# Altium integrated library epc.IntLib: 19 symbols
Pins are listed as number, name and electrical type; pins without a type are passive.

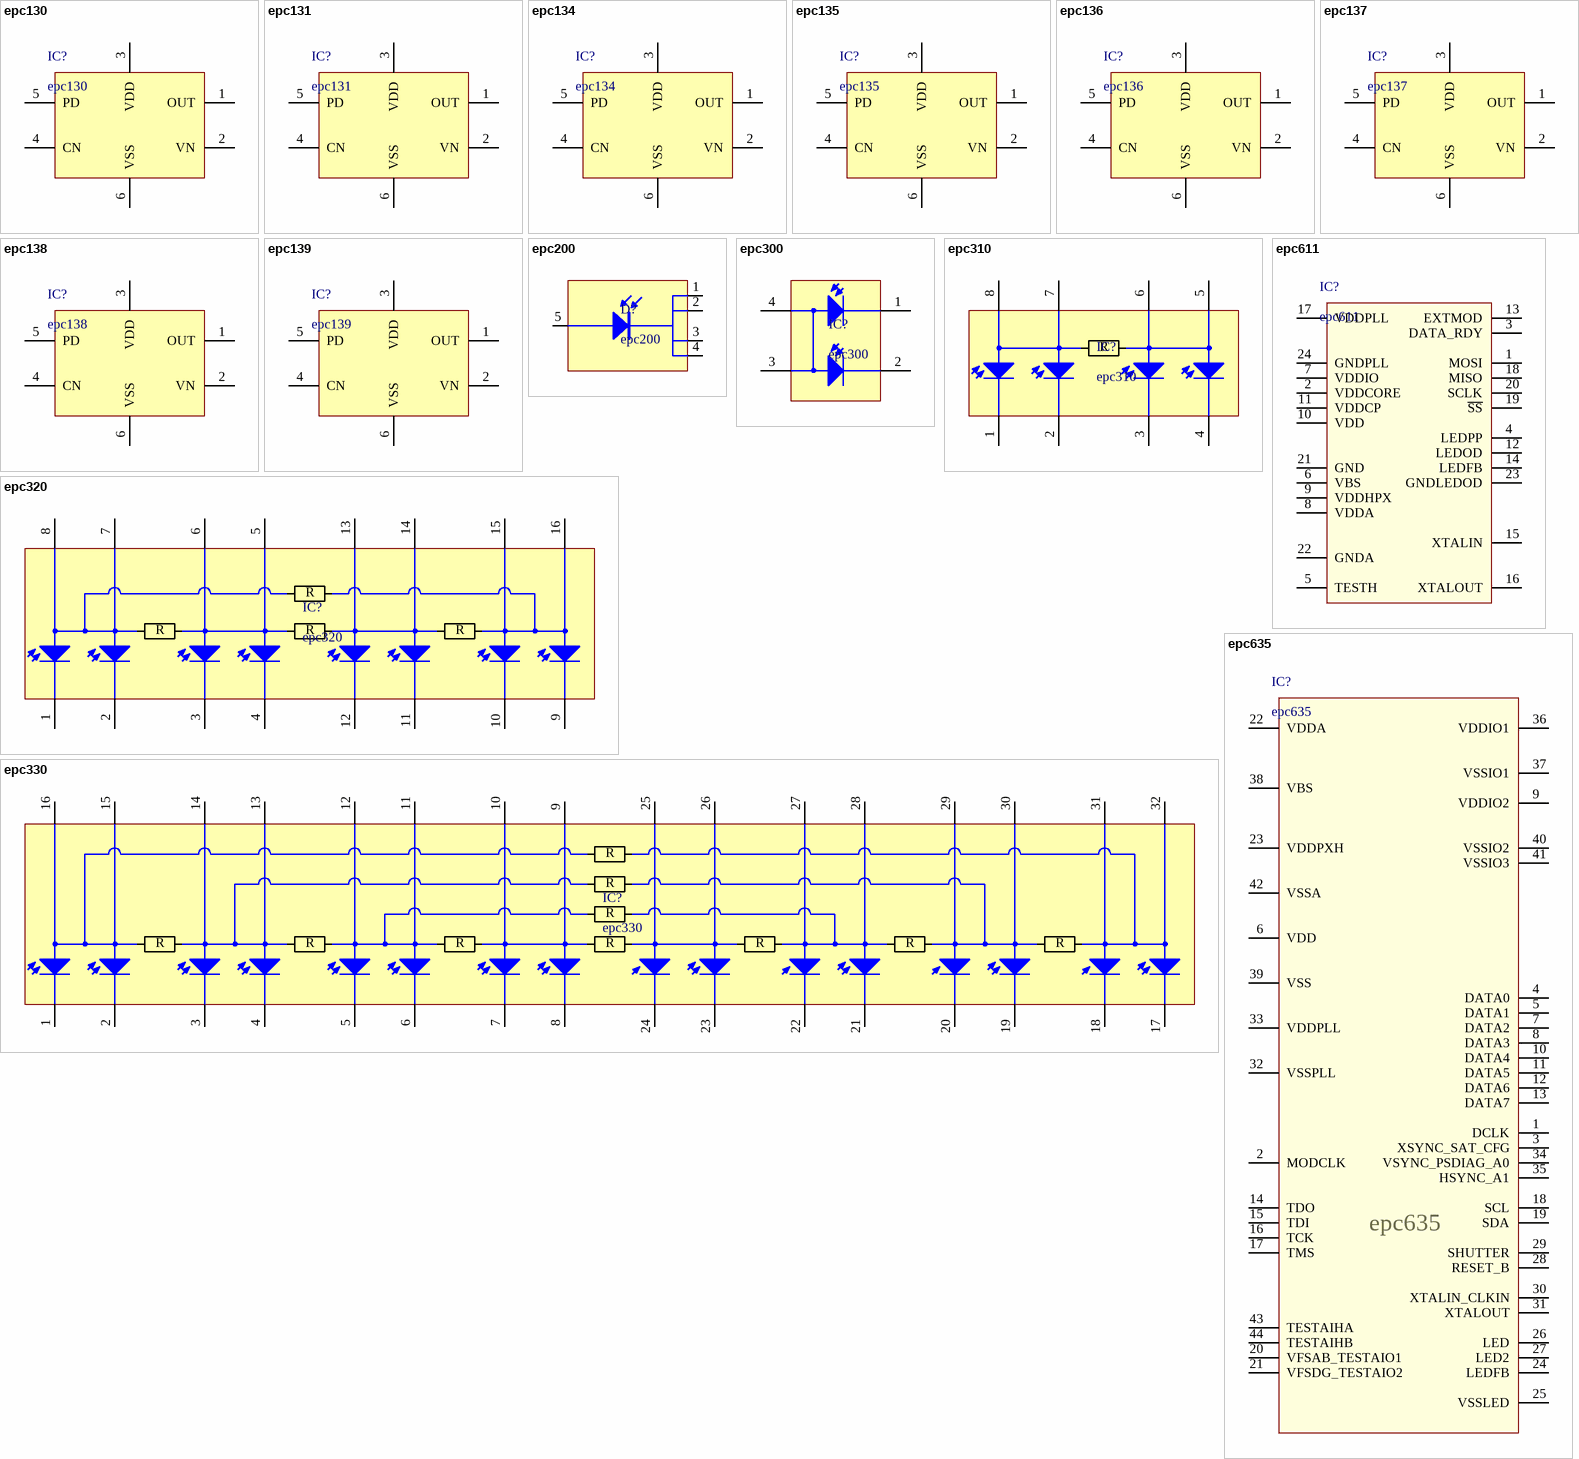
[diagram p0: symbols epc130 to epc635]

## epc130
designator IC?
epc130, Photo-receiver Amplifier with analog output; Part number: P100 010; Manufacturer: ESPROS Photonics; Order information: epc130-CSP6-B; Schlib reviewed: 230418/SHA
footprint CSP 2x3 560x430 (Footprint not found)
pins: 1 OUT, 2 VN, 3 VDD, 4 CN, 5 PD, 6 VSS

## epc131
designator IC?
epc131, Photo-receiver Amplifier with analog output; Part number: P100 011; Manufacturer: ESPROS Photonics; Order information: epc131-CSP6-D; Schlib reviewed: 230418/SHA
footprint CSP 2x3 560x430 (CSP 2x3)
pins: 1 OUT, 2 VN, 3 VDD, 4 CN, 5 PD, 6 VSS

## epc134
designator IC?
epc134, Photo-receiver Amplifier with digital output; Part number: P100 491; Manufacturer: ESPROS Photonics; Order information: epc134-CSP6-D; Schlib reviewed: 230418/SHA
footprint CSP 2x3 560x430 (CSP 2x3)
pins: 1 OUT, 2 VN, 3 VDD, 4 CN, 5 PD, 6 VSS

## epc135
designator IC?
epc135, Photo-receiver Amplifier with digital output; Part number: P100 012; Manufacturer: ESPROS Photonics; Order information: epc135-CSP6-B; Schlib reviewed: 230418/SHA
footprint CSP 2x3 560x430 (CSP 2x3)
pins: 1 OUT, 2 VN, 3 VDD, 4 CN, 5 PD, 6 VSS

## epc136
designator IC?
epc136, Photo-receiver Amplifier with digital output; Part number: P100 013; Manufacturer: ESPROS Photonics; Order information: epc136-CSP6-B; Schlib reviewed: 230418/SHA
footprint CSP 2x3 560x430 (CSP 2x3)
pins: 1 OUT, 2 VN, 3 VDD, 4 CN, 5 PD, 6 VSS

## epc137
designator IC?
epc137, Photo-receiver Amplifier with digital output; Part number: P100 152; Manufacturer: ESPROS Photonics; Order information: epc137-CSP6-D; Schlib reviewed: 230418/SHA
footprint CSP 2x3 560x430 (CSP 2x3)
pins: 1 OUT, 2 VN, 3 VDD, 4 CN, 5 PD, 6 VSS

## epc138
designator IC?
epc138, Photo-receiver Amplifier with digital output; Part number: P100 109; Manufacturer: ESPROS Photonics; Order information: epc138-CSP6-D; Schlib reviewed: 230418/SHA
footprint CSP 2x3 560x430 (CSP 2x3)
pins: 1 OUT, 2 VN, 3 VDD, 4 CN, 5 PD, 6 VSS

## epc139
designator IC?
epc139, Photo-receiver Amplifier with digital output; Part number: P100 014; Manufacturer: ESPROS Photonics; Order information: epc139-CSP6-B; Schlib reviewed: 230418/SHA
footprint CSP 2x3 560x430 (CSP 2x3)
pins: 1 OUT, 2 VN, 3 VDD, 4 CN, 5 PD, 6 VSS

## epc200
designator D?
epc200, High sensitive photodiode; Part number: P100 179; Manufacturer: ESPROS Photonics; Order information: epc200-CSP5; Schlib reviewed: 230418/SHA; Pcblib reviewed: already existed
footprint epc200
pins: 1 C, 2 C, 3 C, 4 C, 5 A

## epc300
designator IC?
epc300, high sensitive photodiode array with 2 photodiodes; Part number: P100 049; Manufacturer: ESPROS Photonics; Order information: epc300-CSP4-001; Schlib reviewed: 230418/SHA
footprint CSP4 (CSP4 Dual Photodiode)
pins: 1 C1, 2 C2, 3 A2, 4 A1

## epc310
designator IC?
epc310, high sensitive photodiode array with 4 photodiodes; Part number: P100 050; Manufacturer: ESPROS Photonics; Order information: epc310-CSP8-001; Schlib reviewed: 230418/SHA
footprint CSP8 (CSP8 Quad Photodiode-Array)
pins: 1 C1, 2 C2, 3 C3, 4 C4, 5 A4, 6 A3, 7 A2, 8 A1

## epc320
designator IC?
epc320, high sensitive photodiode array with 8 photodiodes; Part number: P100 051; Manufacturer: ESPROS Photonics; Order information: epc320-CSP16-001; Schlib reviewed: 230418/SHA
footprint CSP16 (CSP16 Octa Photodiode-Array)
pins: 1 C1, 2 C2, 3 C3, 4 C4, 5 A4, 6 A3, 7 A2, 8 A1, 9 C5, 10 C6, 11 C7, 12 C8, 13 A8, 14 A7, 15 A6, 16 A5

## epc330
designator IC?
epc330, high sensitive photodiode array with 16 photodiodes; Part number: P100 052; Manufacturer: ESPROS Photonics; Order information: epc330-CSP32-001; Schlib reviewed: 230418/SHA
footprint CSP32 (CSP16 hexa Photodiode-Array)
pins: 1 C1, 2 C2, 3 C3, 4 C4, 5 C5, 6 C6, 7 C7, 8 C8, 9 A8, 10 A7, 11 A6, 12 A5, 13 A4, 14 A3, 15 A2, 16 A1, 17 C9, 18 C10, 19 C11, 20 C12, 21 C13, 22 C14, 23 C15, 24 C16, 25 A16, 26 A15, 27 A14, 28 A13, 29 A12, 30 A11, 31 A10, 32 A9

## epc611
designator IC?
epc611, TOF range-finder / 8x8 pixel TOF imager; Part number: P100 378; Manufacturer: ESPROS Photonics; Order information: epc611-CSP-000; SchLib reviewed: 230228/SHA; PcbLib reviewed: 210707/ROD
footprint epc611
pins: 1 MOSI, 2 VDDCORE, 3 DATA_RDY, 4 LEDPP, 5 TESTH, 6 VBS, 7 VDDIO, 8 VDDA, 9 VDDHPX, 10 VDD, 11 VDDCP, 12 LEDOD, 13 EXTMOD, 14 LEDFB, 15 XTALIN, 16 XTALOUT, 17 VDDPLL, 18 MISO, 19 ~{SS}, 20 SCLK, 21 GND, 22 GNDA, 23 GNDLEDOD, 24 GNDPLL

## epc635
designator IC?
epc635-CSP44-003, 3D TOF imager 160 x 60 pixel; Part number: P100 181; Manufacturer: ESPROS Photonics; Schlib reviewed: 230220/SHA; Pcblib reviewed: already existed
footprint epc635_Plane_Top (CSP44 epc635_PL_Top)
pins: 1 DCLK, 2 MODCLK, 3 XSYNC_SAT_CFG, 4 DATA0, 5 DATA1, 6 VDD, 7 DATA2, 8 DATA3, 9 VDDIO2, 10 DATA4, 11 DATA5, 12 DATA6, 13 DATA7, 14 TDO, 15 TDI, 16 TCK, 17 TMS, 18 SCL, 19 SDA, 20 VFSAB_TESTAIO1, 21 VFSDG_TESTAIO2, 22 VDDA, 23 VDDPXH, 24 LEDFB, 25 VSSLED, 26 LED, 27 LED2, 28 RESET_B, 29 SHUTTER, 30 XTALIN_CLKIN, 31 XTALOUT, 32 VSSPLL, 33 VDDPLL, 34 VSYNC_PSDIAG_A0, 35 HSYNC_A1, 36 VDDIO1, 37 VSSIO1, 38 VBS, 39 VSS, 40 VSSIO2, 41 VSSIO3, 42 VSSA, 43 TESTAIHA, 44 TESTAIHB

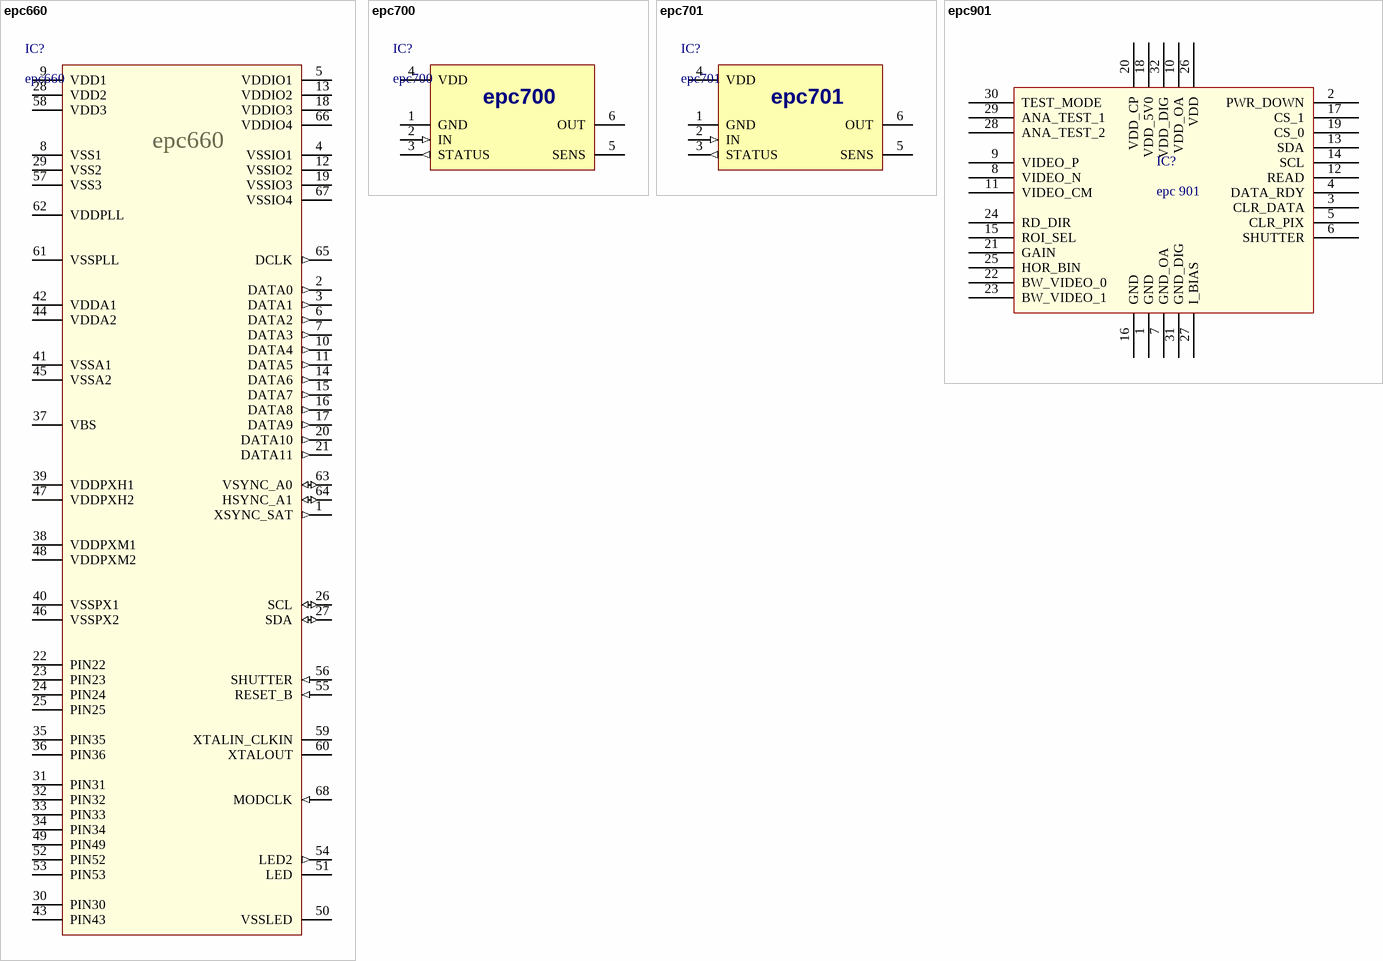
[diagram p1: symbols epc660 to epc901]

## epc660
designator IC?
epc660, 3D TOF imager 320 x 240 pixel; Part number: P100 688; Manufacturer: ESPROS Photonics; Order information: epc660-CSP68-011; Schlib reviewed: 230418/SHA
footprint epc660_Plane_Top (CSP68 epc660_PL_Top)
pins: 1 XSYNC_SAT (out), 2 DATA0 (out), 3 DATA1 (out), 4 VSSIO1 (power), 5 VDDIO1 (power), 6 DATA2 (out), 7 DATA3 (out), 8 VSS1 (power), 9 VDD1 (power), 10 DATA4 (out), 11 DATA5 (out), 12 VSSIO2 (power), 13 VDDIO2 (power), 14 DATA6 (out), 15 DATA7 (out), 16 DATA8 (out), 17 DATA9 (out), 18 VDDIO3 (power), 19 VSSIO3 (power), 20 DATA10 (out), 21 DATA11 (out), 22 PIN22, 23 PIN23, 24 PIN24, 25 PIN25, 26 SCL (io), 27 SDA (io), 28 VDD2 (power), 29 VSS2 (power), 30 PIN30, 31 PIN31, 32 PIN32, 33 PIN33, 34 PIN34, 35 PIN35, 36 PIN36, 37 VBS (power), 38 VDDPXM1 (power), 39 VDDPXH1 (power), 40 VSSPX1 (power), 41 VSSA1 (power), 42 VDDA1 (power), 43 PIN43, 44 VDDA2 (power), 45 VSSA2 (power), 46 VSSPX2 (power), 47 VDDPXH2 (power), 48 VDDPXM2 (power), 49 PIN49, 50 VSSLED (power), 51 LED (oc), 52 PIN52, 53 PIN53, 54 LED2 (out), 55 RESET_B (in), 56 SHUTTER (in), 57 VSS3 (power), 58 VDD3 (power), 59 XTALIN_CLKIN, 60 XTALOUT, 61 VSSPLL (power), 62 VDDPLL (power), 63 VSYNC_A0 (io), 64 HSYNC_A1 (io), 65 DCLK (out), 66 VDDIO4 (power), 67 VSSIO4 (power), 68 MODCLK (in)

## epc700
designator IC?
epc700 General Purpose Output Driver Low-Side Switch CSP-6; Part number: P100 009; Manufacturer: ESPROS Photonics; Order information: epc700-CSP6-A; Schlib reviewed: 230418/SHA
footprint CSP 2x3 560x430 (CSP 2x3)
pins: 1 GND (power), 2 IN (in), 3 STATUS (out), 4 VDD (power), 5 SENS, 6 OUT (oc)

## epc701
designator IC?
epc701 General Purpose Output Driver High-Side Switch CSP-6; Part number: P100 039; Manufacturer: ESPROS Photonics; Order information: epc701-CSP6-A; Schlib reviewed: 230418/SHA
footprint CSP 2x3 560x430 (CSP 2x3)
pins: 1 GND (power), 2 IN (in), 3 STATUS (out), 4 VDD (power), 5 SENS, 6 OUT (oc)

## epc901
designator IC?, comment epc 901
epc901, CCD line sensor 1024 x 1 pixel; Part number: P100 401; Manufacturer: ESPROS Photonics; Order information: epc901-CSP32-033; Schlib reviewed: 221004/SHA
footprint epc901
pins: 1 GND, 2 PWR_DOWN, 3 CLR_DATA, 4 DATA_RDY, 5 CLR_PIX, 6 SHUTTER, 7 GND_OA, 8 VIDEO_N, 9 VIDEO_P, 10 VDD_OA, 11 VIDEO_CM, 12 READ, 13 SDA, 14 SCL, 15 ROI_SEL, 16 GND, 17 CS_1, 18 VDD_5V0, 19 CS_0, 20 VDD_CP, 21 GAIN, 22 BW_VIDEO_0, 23 BW_VIDEO_1, 24 RD_DIR, 25 HOR_BIN, 26 VDD, 27 I_BIAS, 28 ANA_TEST_2, 29 ANA_TEST_1, 30 TEST_MODE, 31 GND_DIG, 32 VDD_DIG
